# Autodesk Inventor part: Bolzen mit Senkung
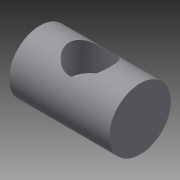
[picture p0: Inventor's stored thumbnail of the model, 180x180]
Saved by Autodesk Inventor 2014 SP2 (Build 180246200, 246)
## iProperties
Created: 2015-04
Part Number: Bolzen mit Senkung
Material: Generisch
Document SubType Name: Modeling
Designer: e_krauts
Density: 1 g/cm^3
Appearance: Vorgabe
Author: e_krauts
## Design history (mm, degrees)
sketch "Skizze1"
  geometry: C1 r 10 at (0, 0); 1 further point
  constraints: 1 centre point, 1 coincident
  dimensions: "d0" = 20 diameter of C1
extrude "Extrusion1" new body sketch "Skizze1" distance "d1" = 32.5; taper "d2" = 0 deg
workplane "Arbeitsebene1"
sketch "Skizze2"
  geometry: L1 (-10, 0)-(10, 0) reference; 2 further points
  dimensions: "d3" = 16.25 distance from line of L1 point (0, -16.25)
hole "Bohrung1" sketch "Skizze2" at (0, -16.25) diameter "d4" = 8.5; stored, may be unused: countersink angle "d8" = 90 deg, drill point angle "d10" = 118 deg; dims "d5" = 6, "d6" = 13.5, "d7" = 10, "d9" = 8
node "Volumenkörper1"
